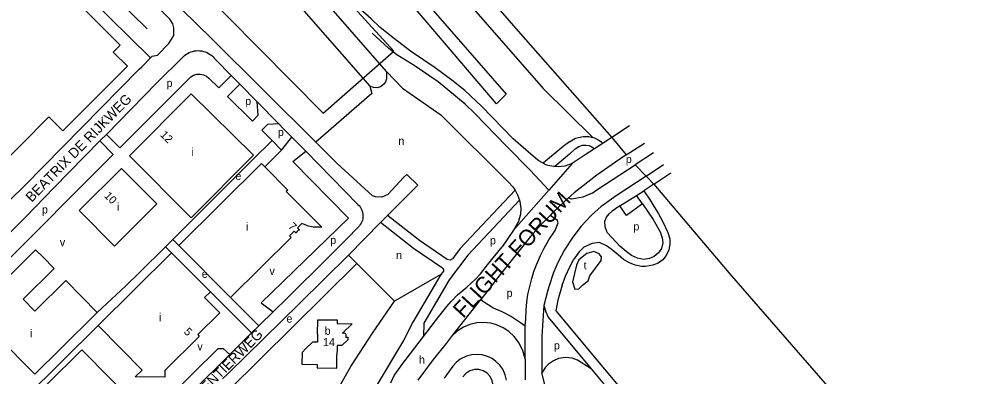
# Model space of a CAD drawing. Extents: x 154765 to 156627, y 383996 to 386132.
# Drawn here: x 155749.2 to 156222.1, y 385236.2 to 385414.8 of the extents above; entities that cross this region are included whole.
import ezdxf

# ---------------------------------------------------------------- set-up
doc = ezdxf.new("R2010")
doc.units = 0
for name, color, linetype in [('BLT_Basislijn', 7, 'Continuous'), ('BLT_Bebouwing', 7, 'Continuous'), ('BLT_Centroide', 7, 'Continuous'), ('BLT_Huisnummer', 7, 'Continuous'), ('BLT_Plantopo', 7, 'Continuous'), ('BLT_Straatnaam', 7, 'Continuous'), ('BLT_Straatnaam_hoofdweg', 7, 'Continuous'), ('BLT_Vlakafsluiter', 7, 'Continuous')]:
    doc.layers.add(name, color=color, linetype=linetype)

msp = doc.modelspace()

# ---------------------------------------------------------------- linework, layer by layer
at = {"layer": 'BLT_Basislijn'}
for p, q in [((155868.56, 385520.1), (155992.72, 385377.25)), ((155813.32, 385409.81), (155707.88, 385514.52)), ((155932.89, 385388.5), (155821.88, 385516.23)), ((155814.19, 385507.85), (155924.61, 385381.18)), ((155704.4, 385504.85), (155814.96, 385395.3)), ((155988, 385372.42), (155879.01, 385500)), ((155810.63, 385390.94), (155814.96, 385395.3)), ((155818.05, 385382.73), (155831.28, 385395.89)), ((155847.42, 385394.56), (155855.27, 385386.58)), ((155834.12, 385384.85), (155799.71, 385350.36)), ((155849.08, 385380.35), (155844.09, 385385.27)), ((155855.27, 385386.58), (155849.08, 385380.35)), ((155855.27, 385386.58), (155859.58, 385382.19)), ((155859.58, 385382.19), (155853.46, 385376.03)), ((155859.58, 385382.19), (155868.32, 385373.31)), ((155865.94, 385363.71), (155853.46, 385376.03)), ((155992.72, 385377.25), (155988, 385372.42)), ((155868.32, 385373.31), (155878.95, 385362.49)), ((155878.95, 385362.49), (155881.68, 385359.71)), ((155792.95, 385357.08), (155789.7, 385353.77)), ((155792.95, 385357.08), (155799.71, 385350.36)), ((155875.82, 385353.97), (155870.61, 385359.11)), ((155881.68, 385359.71), (155885.57, 385355.75)), ((155789.7, 385353.77), (155796.43, 385347.07)), ((155866.15, 385344.48), (155875.82, 385353.97)), ((155875.82, 385353.97), (155880.47, 385349.25)), ((155880.47, 385349.25), (155885.57, 385355.75)), ((155885.57, 385355.75), (155892.57, 385348.64)), ((156024.46, 385353.39), (156027.43, 385355.16)), ((156027.43, 385355.16), (156028.98, 385355.53)), ((156041.26, 385352.69), (156036.88, 385349.82)), ((156045.62, 385355.54), (156041.26, 385352.69)), ((155796.43, 385347.07), (155710.35, 385260.77)), ((155880.47, 385349.25), (155872.13, 385340.81)), ((155886.08, 385343.56), (155892.57, 385348.64)), ((155892.57, 385348.64), (155918.7, 385322.06)), ((156024.36, 385347.13), (156017.02, 385340.94)), ((155866.15, 385344.48), (155826.23, 385304.48)), ((156014.08, 385329.19), (156004.72, 385339.14)), ((156066.63, 385332.11), (156075.1, 385337.75)), ((155941.68, 385335.59), (155943.05, 385337.03)), ((155943.05, 385337.03), (155948.58, 385331.62)), ((156062.72, 385336.17), (156047.78, 385326.29)), ((155947.12, 385330.18), (155940.21, 385323.38)), ((155948.58, 385331.62), (155947.12, 385330.18)), ((156057.86, 385326.54), (156061.53, 385328.87)), ((156066.63, 385332.11), (156061.53, 385328.87)), ((155940.21, 385323.38), (155933.51, 385316.56)), ((156049.54, 385321.27), (156057.86, 385326.54)), ((156060.88, 385322.32), (156057.86, 385326.54)), ((156040.33, 385320.99), (156035.37, 385316.63)), ((156041.21, 385321.63), (156040.33, 385320.99)), ((156042.44, 385322.52), (156041.21, 385321.63)), ((156045.7, 385318.67), (156044.27, 385317.34)), ((156047.4, 385319.9), (156045.7, 385318.67)), ((156049.54, 385321.27), (156047.4, 385319.9)), ((155933.51, 385316.56), (155929.98, 385312.97)), ((156035.37, 385316.63), (156030.26, 385311.1)), ((155919.14, 385311.01), (155912.75, 385304.47)), ((155929.98, 385312.97), (155913.97, 385296.7)), ((156030.26, 385311.1), (156026.12, 385305.67)), ((155826.23, 385304.48), (155822.57, 385300.86)), ((155829.21, 385301.49), (155826.23, 385304.48)), ((155996.51, 385309.15), (155990.82, 385300.82)), ((156026.12, 385305.67), (156021.97, 385299.29)), ((155822.57, 385300.86), (155809.6, 385288.06)), ((155825.58, 385297.86), (155822.57, 385300.86)), ((155983.51, 385291.81), (155990.82, 385300.82)), ((156021.97, 385299.29), (156018.78, 385293.23)), ((155853.99, 385229.02), (155918.18, 385292.41)), ((155979.9, 385287.26), (155983.51, 385291.81)), ((156018.78, 385293.23), (156016.44, 385288.02)), ((156022.5, 385286.21), (156024.63, 385290.89)), ((156024.63, 385290.89), (156026.65, 385294.72)), ((155960.16, 385287.01), (155936.99, 385273.7)), ((155977.39, 385284.59), (155979.9, 385287.26)), ((156016.44, 385288.02), (156014.21, 385281.32)), ((156020.7, 385281.64), (156022.5, 385286.21)), ((155973.16, 385280.67), (155977.39, 385284.59)), ((156014.21, 385281.32), (156013.57, 385279.19)), ((156020.7, 385281.64), (156018.56, 385274.15)), ((155865.56, 385257.72), (155844.92, 385278.36)), ((155965.31, 385273.45), (155968.45, 385276.74)), ((155968.45, 385276.74), (155973.16, 385280.67)), ((156013.57, 385279.19), (156011.54, 385271.39)), ((155863.79, 385266.64), (155854.94, 385275.48)), ((155870.25, 385272.88), (155876.3, 385268.35)), ((155963.12, 385270.94), (155965.31, 385273.45)), ((156011.54, 385271.39), (156011.03, 385264.11)), ((156018.56, 385274.15), (156017.6, 385268.87)), ((155869.15, 385261.27), (155863.79, 385266.64)), ((155959.09, 385265.95), (155963.12, 385270.94)), ((155946.07, 385263.09), (155941.45, 385253.88)), ((155951.48, 385255.98), (155959.09, 385265.95)), ((155951.57, 385262.58), (155951.48, 385255.98)), ((156011.03, 385264.11), (156010.53, 385255.83)), ((155788.81, 385261.42), (155741.91, 385215.01)), ((155854.62, 385246.9), (155865.56, 385257.72)), ((155865.56, 385257.72), (155869.15, 385261.27)), ((155869.15, 385261.27), (155869.7, 385261.82)), ((155941.45, 385253.88), (155927.86, 385231.1)), ((155945.02, 385247.52), (155951.48, 385255.98)), ((155956.52, 385244.53), (155962.99, 385252.49)), ((155962.99, 385252.49), (155965.94, 385256.49)), ((156010.53, 385255.83), (156010.53, 385237.8)), ((155848.75, 385250), (155800.59, 385202.43)), ((155941.09, 385242.43), (155945.02, 385247.52)), ((155948.82, 385234.08), (155956.52, 385244.53)), ((156002.26, 385244.8), (156002.26, 385234.33)), ((155936.86, 385236.47), (155941.09, 385242.43)), ((155853.77, 385237.45), (155850.97, 385234.72)), ((155935.13, 385232.86), (155936.86, 385236.47))]:
    msp.add_line(p, q, dxfattribs=at)
for points in [[(155733.11, 385703.62), (155742.99, 385690.24), (155782.23, 385642.23), (156011.28, 385380.1), (156036.1, 385355.51)], [(156007.6, 385344.92), (155996.28, 385354.88), (155980.49, 385371.12), (155972.14, 385379.04), (155965.68, 385384.27), (155957.28, 385390.42), (155944.89, 385398.75), (155936.89, 385404.83), (155929.87, 385410.58), (155925.23, 385414.81), (155918.35, 385421.09), (155902.63, 385438.73), (155854.03, 385494.81), (155800.47, 385556.64), (155793.89, 385564.54), (155785.69, 385576.1), (155777.93, 385590.57), (155771.46, 385606.33), (155765, 385622.09), (155759.19, 385632.12), (155752.51, 385642.23), (155748.51, 385647.55), (155714.99, 385688.08)], [(155814.96, 385395.3), (155815.81, 385396.15), (155818.5, 385396.69), (155824.21, 385402.45), (155826.6, 385406.47), (155826.75, 385410.3), (155826.12, 385412.36), (155824.68, 385414.68), (155714.02, 385524.27)], [(155919.37, 385500), (156000, 385407.31), (156045.62, 385355.54)], [(155770.64, 385478.39), (155845.5, 385405.08)], [(155845.5, 385405.08), (155897.59, 385353.15)], [(156004.72, 385339.14), (155992.94, 385351.23), (155977.1, 385367.51), (155972.31, 385372.1), (155958.75, 385383.41), (155946.78, 385391.57), (155938.17, 385396.94), (155934.11, 385400), (155925.77, 385407.68)], [(155831.28, 385395.89), (155831.96, 385396.51), (155832.7, 385397.07), (155833.48, 385397.56), (155834.3, 385397.98), (155835.15, 385398.34), (155836.03, 385398.61), (155836.94, 385398.81), (155837.85, 385398.93), (155838.77, 385398.97), (155839.7, 385398.93), (155840.61, 385398.81), (155841.52, 385398.61), (155842.4, 385398.34), (155843.25, 385397.99), (155844.07, 385397.57), (155844.85, 385397.07), (155845.59, 385396.52), (155846.27, 385395.9), (155846.9, 385395.22), (155847.42, 385394.56)], [(155734.6, 385315.13), (155737.02, 385316.87), (155752.07, 385331.32), (155809.42, 385389.71), (155810.63, 385390.94)], [(155834.12, 385384.85), (155835.19, 385385.87), (155836.57, 385386.69), (155838.17, 385387.16), (155839.86, 385387.24), (155841.5, 385386.89), (155842.93, 385386.2), (155844.09, 385385.27)], [(155932.89, 385388.5), (155933.02, 385386.55), (155933, 385384.92), (155932.49, 385383.34), (155931.54, 385381.99), (155929.99, 385380.86), (155928.29, 385380.35), (155926.4, 385380.44), (155924.61, 385381.18)], [(155932.89, 385388.5), (155940.98, 385380.19), (155960.09, 385366.88)], [(155792.95, 385357.08), (155818.05, 385382.73)], [(155924.61, 385381.18), (155925.58, 385377.52), (155897.59, 385353.15)], [(155865.94, 385363.71), (155868.88, 385366.69), (155868.32, 385373.31)], [(155960.09, 385366.88), (155994.05, 385333.01), (155996.08, 385330.91), (155997.3, 385329.2)], [(155870.61, 385359.11), (155873.65, 385362.18), (155878.95, 385362.49)], [(156054.38, 385361.28), (156045.62, 385355.54)], [(155766.75, 385330.32), (155789.7, 385353.77)], [(155897.59, 385353.15), (155908.22, 385342.55)], [(156024.46, 385353.39), (156021.27, 385351.07), (156011.47, 385342.8), (156011.24, 385342.59)], [(156028.98, 385355.53), (156031.19, 385356.06), (156034.1, 385355.96), (156036.1, 385355.51)], [(156036.1, 385355.51), (156036.94, 385355.32), (156039.06, 385354.25), (156040.42, 385353.42), (156041.26, 385352.69)], [(156052.77, 385346.77), (156061.84, 385352.71)], [(156024.36, 385347.13), (156027.27, 385349.81), (156029.09, 385351.01), (156030.88, 385351.6), (156032.61, 385351.72), (156034.2, 385351.43), (156035.62, 385350.83), (156036.88, 385349.82)], [(156036.88, 385349.82), (156032.22, 385346.76), (156025.78, 385342.54)], [(156066.34, 385347.8), (156057.26, 385341.85)], [(155886.08, 385343.56), (155914.05, 385315.19), (155870.25, 385272.88)], [(155941.68, 385335.59), (155933.62, 385327), (155930.6, 385325.6), (155927.48, 385325.76), (155925.88, 385326.27), (155908.22, 385342.55)], [(156011.24, 385342.59), (156009.14, 385343.77), (156007.6, 385344.92)], [(156017.02, 385340.94), (156016.52, 385340.97), (156013.59, 385341.54), (156011.94, 385342.2), (156011.24, 385342.59)], [(156025.78, 385342.54), (156022.16, 385341.23), (156018.79, 385340.83), (156017.02, 385340.94)], [(156052.77, 385346.77), (156047.4, 385343.25), (156038.02, 385336.73), (156026.75, 385327.87), (156023.79, 385325.08)], [(156035.77, 385327.63), (156038.66, 385329.65), (156057.26, 385341.85)], [(156062.72, 385336.17), (156071.44, 385341.95)], [(155715.76, 385278.56), (155752.64, 385315.9), (155766.75, 385330.32)], [(155997.3, 385329.2), (155969.83, 385299.94), (155966.01, 385294.82), (155964.84, 385294.22), (155963.36, 385294.49)], [(155997.3, 385329.2), (155997.31, 385329.17), (155998.51, 385326.91), (155999.42, 385324.16)], [(156061.53, 385328.87), (156064.76, 385324.22), (156066.82, 385320.76), (156068.67, 385317.62), (156071.14, 385313.26), (156073.65, 385307.99), (156074.51, 385304.86)], [(156066.63, 385332.11), (156104.27, 385287.64), (156174.32, 385206.92), (156233.92, 385138.38)], [(155999.42, 385324.16), (155973.67, 385296.72), (155964.33, 385284.24), (155951.57, 385262.58)], [(155999.42, 385324.16), (155999.66, 385323.45), (156000.08, 385320), (155999.92, 385317.1), (155998.9, 385313.49), (155996.51, 385309.15)], [(156035.77, 385327.63), (156031.01, 385325.67), (156025.53, 385324.62), (156023.79, 385325.08)], [(156047.78, 385326.29), (156043.01, 385322.93), (156042.44, 385322.52)], [(155918.7, 385322.06), (155919.25, 385321.49), (155919.74, 385320.88), (155920.17, 385320.21), (155920.53, 385319.5), (155920.82, 385318.76), (155921.02, 385318), (155921.16, 385317.22), (155921.21, 385316.43), (155921.18, 385315.64), (155921.07, 385314.86), (155920.89, 385314.09), (155920.62, 385313.34), (155920.29, 385312.62), (155919.88, 385311.94), (155919.41, 385311.31), (155919.14, 385311.01)], [(156060.88, 385322.32), (156066.29, 385314.49), (156069.81, 385308.27), (156070.71, 385305.24), (156071.09, 385302.86), (156070.42, 385300.06), (156068.86, 385297.88), (156066.82, 385296.03), (156064.35, 385294.94), (156061.45, 385294.51), (156058.37, 385295.18), (156055.47, 385296.46), (156052.72, 385298.4), (156049.59, 385301.2), (156045.6, 385305.43), (156043.32, 385307.99), (156042.28, 385310.79), (156042.09, 385313.73), (156042.95, 385315.58), (156044.27, 385317.34)], [(156060.88, 385322.32), (156052.89, 385316.53), (156049.54, 385321.27)], [(155963.36, 385294.49), (155949.47, 385304.05), (155933.51, 385316.56)], [(156014.82, 385316.57), (156010.2, 385311.95), (156004.95, 385305.98), (155999.69, 385299.52), (155988.68, 385285.47), (155986.06, 385282.14), (155980.06, 385274.53)], [(156017.3, 385308.95), (156018.72, 385312.8), (156018.37, 385314.01), (156014.82, 385316.57)], [(155960.91, 385290.11), (155946.51, 385300.01), (155929.98, 385312.97)], [(155876.3, 385268.35), (155883.4, 385275.36), (155903.74, 385295.56), (155912.75, 385304.47)], [(156002.27, 385261.22), (156002.56, 385264.79), (156002.76, 385269.15), (156003.06, 385273.22), (156003.65, 385276.99), (156005.63, 385285.02), (156006.63, 385288.4), (156007.92, 385291.87), (156009.9, 385296.53), (156011.78, 385300.11), (156014.16, 385304.37), (156016.64, 385308.04), (156017.3, 385308.95)], [(156074.51, 385304.86), (156074.6, 385302.1), (156074.08, 385299.26)], [(156074.08, 385299.26), (156072.8, 385296.5), (156071.04, 385294.37), (156068.67, 385292.71), (156066.06, 385291.57), (156062.4, 385290.9), (156060.36, 385290.95), (156057.18, 385291.66), (156054.38, 385292.75), (156051.39, 385294.56), (156048.78, 385296.84), (156045.32, 385299.68), (156042.99, 385301.25), (156039.43, 385302.96), (156035.73, 385302.53), (156031.55, 385300.59), (156029.32, 385298.31), (156026.65, 385294.72)], [(155913.97, 385296.7), (155889.53, 385272.39), (155853.77, 385237.45)], [(155918.18, 385292.41), (155913.97, 385296.7)], [(155936.99, 385273.7), (155918.18, 385292.41)], [(155809.6, 385288.06), (155802.73, 385281.29), (155788.35, 385268.01)], [(155960.16, 385287.01), (155946.07, 385263.09)], [(155960.91, 385290.11), (155961.38, 385289.43), (155961.44, 385288.72), (155960.16, 385287.01)], [(155895.26, 385206.11), (155915.21, 385240.91), (155925.88, 385257.56), (155936.99, 385273.7)], [(155980.06, 385274.53), (155981.43, 385273.4), (155982.9, 385272.41), (155984.61, 385271.39), (155986.31, 385270.37), (155990.53, 385268.41), (155995.43, 385265.96), (156000.01, 385262.95), (156002.27, 385261.22)], [(156011.54, 385271.39), (156012.66, 385268.22), (156013.76, 385265.67), (156035.25, 385239.85)], [(155869.7, 385261.82), (155876.3, 385268.35)], [(156017.6, 385268.87), (156067.1, 385209.39), (156078.36, 385200.71), (156097.68, 385191.32), (156111.76, 385183.48), (156119.51, 385177.89), (156134.36, 385164.83), (156170.3, 385125.55)], [(156002.26, 385244.8), (156001.12, 385249.03), (155999, 385253.16), (155996.8, 385255.97), (155994.05, 385258.46), (155991.23, 385260.28), (155987.96, 385261.8), (155985.1, 385262.61), (155981.5, 385263.02), (155978.1, 385262.76), (155974.58, 385262.01), (155971.39, 385260.66), (155968.24, 385258.61), (155965.94, 385256.49)], [(155848.75, 385250), (155851.33, 385250), (155854.62, 385246.9)], [(155805.18, 385197.99), (155806.26, 385199.07), (155820.08, 385212.74), (155822.76, 385215.43), (155836.2, 385228.68), (155854.62, 385246.9)], [(155992.94, 385234.07), (155992.22, 385236.86), (155991.02, 385239.58), (155989.57, 385241.58), (155987.65, 385243.46), (155985.78, 385244.88), (155983.44, 385245.97), (155980.76, 385246.76), (155978.33, 385246.98), (155975.64, 385246.8), (155972.92, 385246.11), (155969.83, 385244.56), (155967.73, 385242.92), (155966.13, 385241.1), (155961.71, 385235.19)], [(156035.25, 385239.85), (156028.49, 385244.08), (156025.76, 385245.06), (156022.38, 385245.42), (156018.98, 385244.93), (156016.35, 385243.85), (156013.98, 385242.17), (156012.48, 385240.55), (156010.53, 385237.8)], [(156035.25, 385239.85), (156063.61, 385205.77), (156075.71, 385196.44), (156095.37, 385186.88), (156109.07, 385179.25), (156116.39, 385173.98), (156130.85, 385161.25), (156164.98, 385123.97)]]:
    msp.add_lwpolyline(points, dxfattribs=at)
msp.add_lwpolyline([(156036.65, 385298.44), (156033.16, 385297.41), (156029.11, 385294.33), (156027.99, 385291.72), (156025.93, 385283.24), (156027.06, 385279.63), (156029.01, 385279.76), (156030.95, 385281.7), (156033.75, 385283.84), (156034.62, 385286.33), (156040.22, 385294.05), (156040.44, 385295.81), (156039.3, 385297.37)], close=True, dxfattribs=at)
at = {"layer": 'BLT_Bebouwing'}
for p, q in [((155799.88, 385401.72), (155780.3, 385421.17)), ((155854.94, 385275.48), (155829.21, 385301.49)), ((155825.58, 385297.86), (155841.39, 385281.91)), ((155841.39, 385281.91), (155844.92, 385278.36)), ((155731.12, 385263.35), (155757.2, 385237.1))]:
    msp.add_line(p, q, dxfattribs=at)
for points in [[(155716.59, 385357.03), (155736.15, 385337.59), (155764.23, 385365.84), (155771.27, 385358.84), (155803.43, 385391.18), (155796.34, 385398.22), (155799.88, 385401.72)], [(155829.21, 385301.49), (155870.53, 385342.43), (155872.13, 385340.81)], [(155872.13, 385340.81), (155883.62, 385329.23), (155882.81, 385328.43), (155900.6, 385310.64), (155896.23, 385310.64), (155894.04, 385311.19), (155890.69, 385312.51), (155888.51, 385310.32), (155889.45, 385309.29), (155888.87, 385309.05), (155888, 385308.18), (155887.74, 385307.61), (155886.77, 385308.58), (155884.52, 385306.36), (155885.32, 385305.55), (155854.94, 385275.48)], [(155726.28, 385268.19), (155742.47, 385284.29), (155757.61, 385299.32), (155761.13, 385295.77), (155766.88, 385289.95), (155751.34, 385274.61), (155757.26, 385268.66), (155772.77, 385283.98), (155788.35, 385268.01)], [(155788.81, 385261.42), (155825.58, 385297.86)], [(155844.92, 385278.36), (155842.07, 385275.52), (155849.65, 385267.82), (155838.59, 385256.88), (155839.4, 385256), (155822.17, 385238.88), (155822.14, 385235.68), (155807.37, 385235.76), (155810.81, 385239.18), (155800.11, 385250), (155788.81, 385261.42)], [(155757.2, 385237.1), (155770.2, 385250), (155788.35, 385268.01)], [(155898.53, 385257.16), (155898.6, 385264.37), (155908.28, 385264.28), (155908.27, 385262.44), (155915.88, 385262.37), (155911.01, 385257.59), (155911.08, 385257.46)], [(155912.56, 385255.66), (155912.74, 385255.91), (155912.85, 385256.2), (155912.88, 385256.5), (155912.83, 385256.8), (155912.71, 385257.08), (155912.52, 385257.32), (155912.27, 385257.5), (155911.99, 385257.61), (155911.68, 385257.64), (155911.38, 385257.59), (155911.1, 385257.47), (155911.08, 385257.46)], [(155898.53, 385257.16), (155898.49, 385253.12), (155895.94, 385253.14), (155892.72, 385249.98), (155890.73, 385248.03), (155890.67, 385242.11)], [(155913.61, 385254.28), (155910.66, 385251.38), (155908.24, 385251.4), (155908.23, 385249.98), (155908.2, 385246.71)], [(155912.56, 385255.66), (155913.63, 385255.65), (155913.61, 385254.28)], [(155794.71, 385208.1), (155802.53, 385215.87), (155792.86, 385225.63), (155798.48, 385231.29), (155794.94, 385234.81), (155780.67, 385249.27), (155762.86, 385231.59)], [(155890.67, 385242.11), (155898.38, 385242.03), (155898.36, 385240.21), (155908.13, 385240.12), (155908.2, 385246.71)], [(155986.21, 385231.6), (155985.81, 385233.78), (155984.79, 385235.87), (155983.2, 385237.6), (155981.25, 385238.79), (155979.16, 385239.38), (155976.88, 385239.39), (155974.62, 385238.74), (155972.65, 385237.49), (155971.18, 385235.84)]]:
    msp.add_lwpolyline(points, dxfattribs=at)
for points in [[(155804.5, 385346.31), (155835.35, 385377.4), (155866.45, 385346.63), (155835.41, 385315.26)], [(155800.58, 385340.05), (155779.31, 385318.92), (155796.94, 385301.2), (155818.2, 385322.33)]]:
    msp.add_lwpolyline(points, close=True, dxfattribs=at)
at = {"layer": 'BLT_Plantopo'}
msp.add_lwpolyline([(155829.91, 385515.55), (155789.2, 385481.21), (155901.28, 385367.72), (155936.62, 385398.66)], close=True, dxfattribs=at)
at = {"layer": 'BLT_Vlakafsluiter'}
for p, q in [((156045.62, 385355.54), (156052.77, 385346.77)), ((156025.78, 385342.54), (156014.08, 385329.19)), ((156066.63, 385332.11), (156062.72, 385336.17)), ((156014.08, 385329.19), (155996.51, 385309.15)), ((155965.94, 385256.49), (155980.06, 385274.53)), ((156002.26, 385244.8), (156002.27, 385261.22)), ((156014.4, 385223.01), (156010.53, 385237.8))]:
    msp.add_line(p, q, dxfattribs=at)
for points in [[(156057.26, 385341.85), (156062.72, 385336.17)], [(156023.79, 385325.08), (156016, 385317.75), (156014.82, 385316.57)]]:
    msp.add_lwpolyline(points, dxfattribs=at)

# ---------------------------------------------------------------- texts
at = {"layer": 'BLT_Centroide'}
for s, p in [('p', (155823.03, 385380.78)), ('p', (155862.31, 385371.75)), ('p', (155878.67, 385356.24)), ('n', (155938.9, 385351.82)), ('i', (155835.48, 385346.31)), ('p', (156052.57, 385342.7)), ('e', (155857.43, 385334.27)), ('p', (155760.78, 385317.49)), ('i', (155798.3, 385318.9)), ('i', (155862.75, 385308.94)), ('p', (156056.35, 385309.03)), ('p', (155904.85, 385302.21)), ('p', (155984.67, 385302.06)), ('v', (155769.69, 385301.13)), ('n', (155937.71, 385294.69)), ('t', (156031.51, 385289.53)), ('e', (155840.62, 385285.3)), ('v', (155874.47, 385286.77)), ('p', (155993.02, 385275.76)), ('i', (155819.23, 385263.62)), ('e', (155882.96, 385262.93)), ('i', (155754.74, 385255.56)), ('b', (155902.04, 385256.83)), ('p', (156016.61, 385249.51)), ('v', (155838.43, 385248.99)), ('h', (155949.19, 385242.36))]:
    msp.add_text(s, height=4, dxfattribs=at).set_placement(p)
at = {"layer": 'BLT_Huisnummer'}
for s, rotation, p in [('12', 315.0362, (155819.59, 385356.54)), ('10', 315.0362, (155791.54, 385326.05)), ('7', 315.0032, (155883.5, 385310.65)), ('5', 314.6965, (155831.37, 385257.99)), ('14', 359.4547, (155901.21, 385251.19))]:
    msp.add_text(s, height=4, rotation=rotation, dxfattribs=at).set_placement(p)
at = {"layer": 'BLT_Straatnaam'}
for s, rotation, p in [('BEATRIX DE RIJKWEG', 45.6209, (155755.62, 385322.82)), ('PARMENTIERWEG', 45.2581, (155829.49, 385214.12))]:
    msp.add_text(s, height=5, rotation=rotation, dxfattribs=at).set_placement(p)
at = {"layer": 'BLT_Straatnaam_hoofdweg'}
msp.add_text('FLIGHT FORUM', height=8, rotation=47.4457, dxfattribs=at).set_placement((155971.27, 385264.71))

doc.saveas('drawing.dxf')
